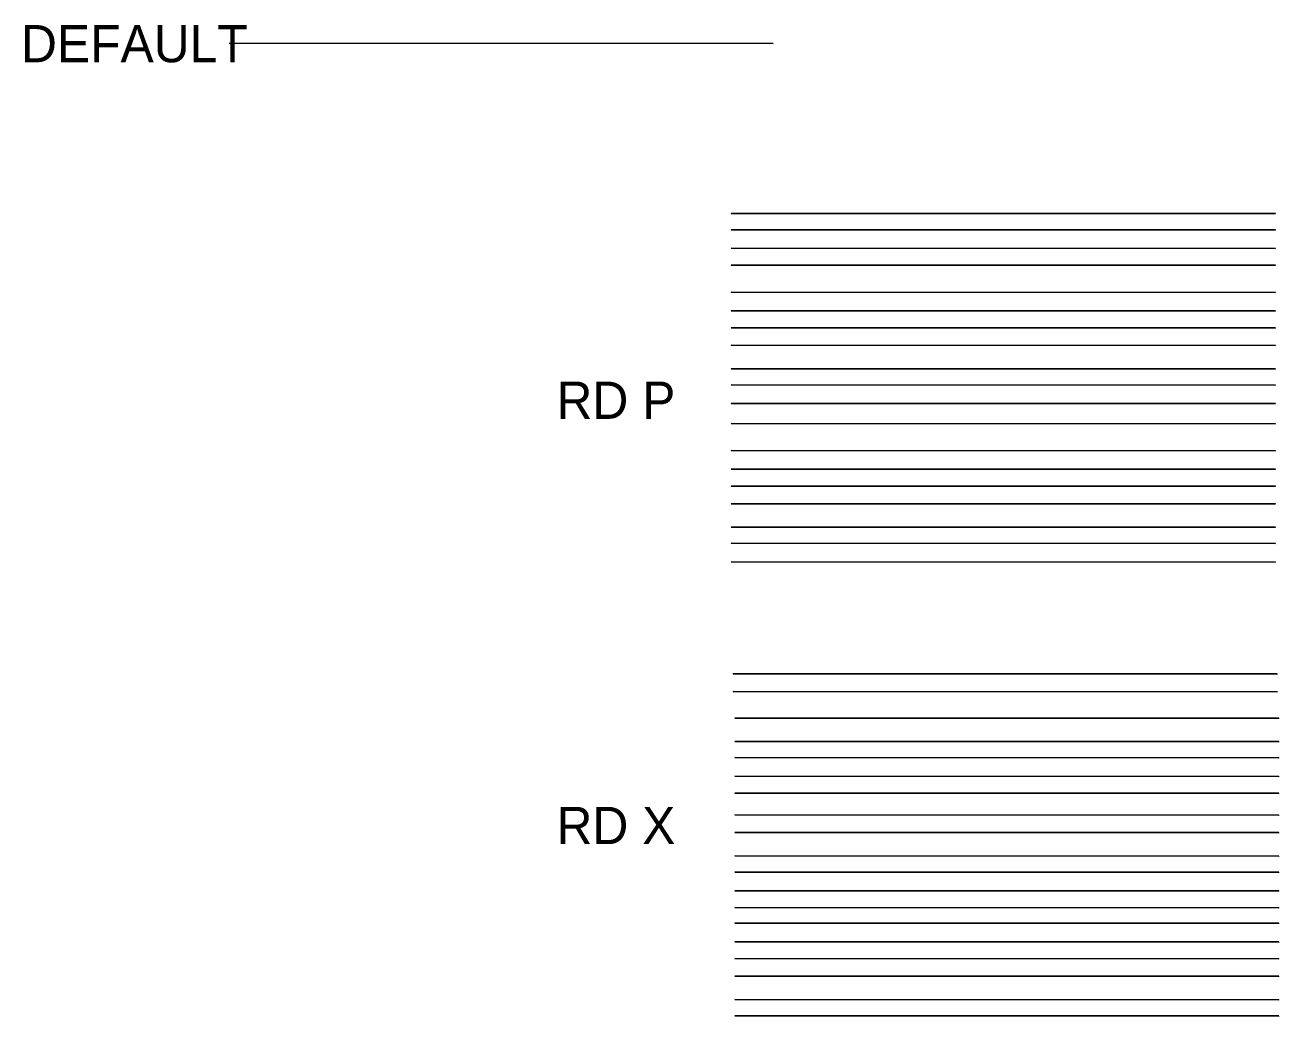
# Model space of a CAD drawing. Extents: x 19437 to 1370217, y 6871 to 405972.
# Drawn here: x 20362 to 22384, y 15649 to 17247 of the extents above; entities that cross this region are included whole.
import ezdxf

# ---------------------------------------------------------------- set-up
doc = ezdxf.new("R2010")
doc.units = 0
for name, color, linetype in [('Default', 7, 'Continuous'), ('RD_P_Anchor_Assembly', 7, 'Continuous'), ('RD_P_Cells', 7, 'Continuous'), ('RD_P_Concrete_Barrier', 7, 'Continuous'), ('RD_P_Delineator_FlexPost', 7, 'Continuous'), ('RD_P_Fence', 7, 'Continuous'), ('RD_P_Gate', 7, 'Continuous'), ('RD_P_GR_Bar', 7, 'Continuous'), ('RD_P_GR_Bar_Replaced', 7, 'Continuous'), ('RD_P_GR_Cable_Bar', 7, 'Continuous'), ('RD_P_GR_Lt', 7, 'Continuous'), ('RD_P_GR_Lt_Replaced', 7, 'Continuous'), ('RD_P_GR_Rt', 7, 'Continuous'), ('RD_P_GR_Rt_Replaced', 7, 'Continuous'), ('RD_P_Median_Barrier', 7, 'Continuous'), ('RD_P_Noise_Wall', 7, 'Continuous'), ('RD_P_RR_1', 7, 'Continuous'), ('RD_P_RR_2', 7, 'Continuous'), ('RD_P_Text', 7, 'Continuous'), ('RD_P_Wall', 7, 'Continuous'), ('RD_X_Anchor_Assembly', 7, 'Continuous'), ('RD_X_Bedrock', 7, 'Continuous'), ('RD_X_Bumper_Block', 7, 'Continuous'), ('RD_X_Cells', 7, 'Continuous'), ('RD_X_Concrete_Barrier', 7, 'Continuous'), ('RD_X_Concrete_Pad', 7, 'Continuous'), ('RD_X_Fence', 7, 'Continuous'), ('RD_X_Gate', 7, 'Continuous'), ('RD_X_GR_Bar', 7, 'Continuous'), ('RD_X_GR_Cable_Bar', 7, 'Continuous'), ('RD_X_GR_Lt', 7, 'Continuous'), ('RD_X_GR_Rt', 7, 'Continuous'), ('RD_X_Misc_Items', 7, 'Continuous'), ('RD_X_Noise_Wall', 7, 'Continuous'), ('RD_X_RR_1', 7, 'Continuous'), ('RD_X_RR_2', 7, 'Continuous'), ('RD_X_RR_Cells', 7, 'Continuous'), ('RD_X_Text', 7, 'Continuous'), ('RD_X_Wall', 7, 'Continuous')]:
    doc.layers.add(name, color=color, linetype=linetype)

msp = doc.modelspace()

# ---------------------------------------------------------------- linework, layer by layer
at = {"layer": 'Default'}
msp.add_line((20690.8, 17218.2), (21568.1, 17217.6), dxfattribs=at)
at = {"layer": 'RD_P_Anchor_Assembly'}
msp.add_lwpolyline([(21500.7, 16943.5), (21500.7, 16943.5), (22378, 16943.3), (22378, 16943.3)], dxfattribs=at)
at = {"layer": 'RD_P_Cells'}
msp.add_lwpolyline([(21500.7, 16917.4), (21500.7, 16917.4), (22378, 16917.2), (22378, 16917.2)], dxfattribs=at)
at = {"layer": 'RD_P_Concrete_Barrier'}
msp.add_lwpolyline([(21500.7, 16887.5), (21500.7, 16887.5), (22378, 16887.3), (22378, 16887.3)], dxfattribs=at)
at = {"layer": 'RD_P_Delineator_FlexPost'}
msp.add_lwpolyline([(21500.7, 16860.1), (21500.7, 16860.1), (22378, 16859.9), (22378, 16859.9)], dxfattribs=at)
at = {"layer": 'RD_P_Fence'}
msp.add_lwpolyline([(21500.7, 16816.5), (21500.7, 16816.5), (22378, 16816.3), (22378, 16816.3)], dxfattribs=at)
at = {"layer": 'RD_P_Gate'}
msp.add_lwpolyline([(21500.7, 16786.5), (21500.7, 16786.5), (22378, 16786.3), (22378, 16786.3)], dxfattribs=at)
at = {"layer": 'RD_P_GR_Bar'}
msp.add_lwpolyline([(21500.7, 16759.1), (21500.7, 16759.1), (22378, 16758.9), (22378, 16758.9)], dxfattribs=at)
at = {"layer": 'RD_P_GR_Bar_Replaced'}
msp.add_lwpolyline([(21500.7, 16730.9), (21500.7, 16730.9), (22378, 16730.7), (22378, 16730.7)], dxfattribs=at)
at = {"layer": 'RD_P_GR_Cable_Bar'}
msp.add_lwpolyline([(21500.7, 16693.1), (21500.7, 16693.1), (22378, 16692.9), (22378, 16692.9)], dxfattribs=at)
at = {"layer": 'RD_P_GR_Lt'}
msp.add_lwpolyline([(21500.7, 16667), (21500.7, 16667), (22378, 16666.8), (22378, 16666.8)], dxfattribs=at)
at = {"layer": 'RD_P_GR_Lt_Replaced'}
msp.add_lwpolyline([(21500.7, 16637), (21500.7, 16637), (22378, 16636.8), (22378, 16636.8)], dxfattribs=at)
at = {"layer": 'RD_P_GR_Rt'}
msp.add_lwpolyline([(21500.7, 16604.7), (21500.7, 16604.7), (22378, 16604.5), (22378, 16604.5)], dxfattribs=at)
at = {"layer": 'RD_P_GR_Rt_Replaced'}
msp.add_lwpolyline([(21500.7, 16561.1), (21500.7, 16561.1), (22378, 16560.9), (22378, 16560.9)], dxfattribs=at)
at = {"layer": 'RD_P_Median_Barrier'}
msp.add_lwpolyline([(21500.7, 16531.1), (21500.7, 16531.1), (22378, 16530.9), (22378, 16530.9)], dxfattribs=at)
at = {"layer": 'RD_P_Noise_Wall'}
msp.add_lwpolyline([(21500.7, 16503.7), (21500.7, 16503.7), (22378, 16503.5), (22378, 16503.5)], dxfattribs=at)
at = {"layer": 'RD_P_RR_1'}
msp.add_lwpolyline([(21500.7, 16475.5), (21500.7, 16475.5), (22378, 16475.3), (22378, 16475.3)], dxfattribs=at)
at = {"layer": 'RD_P_RR_2'}
msp.add_lwpolyline([(21500.7, 16437.7), (21500.7, 16437.7), (22378, 16437.5), (22378, 16437.5)], dxfattribs=at)
at = {"layer": 'RD_P_Text'}
msp.add_lwpolyline([(21500.7, 16411.6), (21500.7, 16411.6), (22378, 16411.4), (22378, 16411.4)], dxfattribs=at)
at = {"layer": 'RD_P_Wall'}
msp.add_lwpolyline([(21500.7, 16381.6), (21500.7, 16381.6), (22378, 16381.4), (22378, 16381.4)], dxfattribs=at)
at = {"layer": 'RD_X_Anchor_Assembly'}
msp.add_lwpolyline([(21506.4, 16129.8), (21506.4, 16129.8), (22383.7, 16129.5), (22383.7, 16129.5)], dxfattribs=at)
at = {"layer": 'RD_X_Bedrock'}
msp.add_lwpolyline([(21506.4, 16092), (21506.4, 16092), (22383.7, 16091.8), (22383.7, 16091.8)], dxfattribs=at)
at = {"layer": 'RD_X_Bumper_Block'}
msp.add_lwpolyline([(21506.4, 16065.9), (21506.4, 16065.9), (22383.7, 16065.7), (22383.7, 16065.7)], dxfattribs=at)
at = {"layer": 'RD_X_Cells'}
msp.add_lwpolyline([(21506.4, 16035.9), (21506.4, 16035.9), (22383.7, 16035.7), (22383.7, 16035.7)], dxfattribs=at)
at = {"layer": 'RD_X_Concrete_Barrier'}
msp.add_lwpolyline([(21506.4, 16008.6), (21506.4, 16008.6), (22383.7, 16008.4), (22383.7, 16008.4)], dxfattribs=at)
at = {"layer": 'RD_X_Concrete_Pad'}
msp.add_lwpolyline([(21506.4, 15973.4), (21506.4, 15973.4), (22383.7, 15973.2), (22383.7, 15973.2)], dxfattribs=at)
at = {"layer": 'RD_X_Fence'}
msp.add_lwpolyline([(21503.6, 16201.1), (21503.6, 16201.1), (22380.9, 16200.9), (22380.9, 16200.9)], dxfattribs=at)
at = {"layer": 'RD_X_Gate'}
msp.add_lwpolyline([(21506.4, 15945.2), (21506.4, 15945.2), (22383.7, 15945), (22383.7, 15945)], dxfattribs=at)
at = {"layer": 'RD_X_GR_Bar'}
msp.add_lwpolyline([(21506.4, 15907.4), (21506.4, 15907.4), (22383.7, 15907.2), (22383.7, 15907.2)], dxfattribs=at)
at = {"layer": 'RD_X_GR_Cable_Bar'}
msp.add_lwpolyline([(21506.4, 15881.3), (21506.4, 15881.3), (22383.7, 15881.1), (22383.7, 15881.1)], dxfattribs=at)
at = {"layer": 'RD_X_GR_Lt'}
msp.add_lwpolyline([(21506.4, 15851.3), (21506.4, 15851.3), (22383.7, 15851.1), (22383.7, 15851.1)], dxfattribs=at)
at = {"layer": 'RD_X_GR_Rt'}
msp.add_lwpolyline([(21506.4, 15824), (21506.4, 15824), (22383.7, 15823.8), (22383.7, 15823.8)], dxfattribs=at)
at = {"layer": 'RD_X_Misc_Items'}
msp.add_lwpolyline([(21506.4, 15799), (21506.4, 15799), (22383.7, 15798.8), (22383.7, 15798.8)], dxfattribs=at)
at = {"layer": 'RD_X_Noise_Wall'}
msp.add_lwpolyline([(21506.4, 15769), (21506.4, 15769), (22383.7, 15768.8), (22383.7, 15768.8)], dxfattribs=at)
at = {"layer": 'RD_X_RR_1'}
msp.add_lwpolyline([(21506.4, 15741.7), (21506.4, 15741.7), (22383.7, 15741.5), (22383.7, 15741.5)], dxfattribs=at)
at = {"layer": 'RD_X_RR_2'}
msp.add_lwpolyline([(21506.4, 15713.4), (21506.4, 15713.4), (22383.7, 15713.2), (22383.7, 15713.2)], dxfattribs=at)
at = {"layer": 'RD_X_RR_Cells'}
msp.add_lwpolyline([(21506.4, 15675.6), (21506.4, 15675.6), (22383.7, 15675.4), (22383.7, 15675.4)], dxfattribs=at)
at = {"layer": 'RD_X_Text'}
msp.add_lwpolyline([(21503.6, 16172.6), (21503.6, 16172.6), (22380.9, 16172.3), (22380.9, 16172.3)], dxfattribs=at)
at = {"layer": 'RD_X_Wall'}
msp.add_lwpolyline([(21506.4, 15649.6), (21506.4, 15649.6), (22383.7, 15649.3), (22383.7, 15649.3)], dxfattribs=at)

# ---------------------------------------------------------------- texts
at = {"layer": 'Default'}
for s, p in [('DEFAULT', (20355.4, 17187.4)), ('RD P', (21218.8, 16612.3)), ('RD X', (21218.8, 15926.5))]:
    msp.add_text(s, height=60, dxfattribs=at).set_placement(p)

doc.saveas('drawing.dxf')
